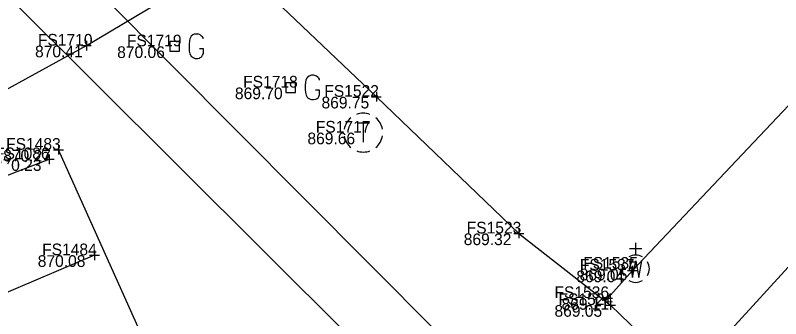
# Model space of a CAD drawing. Extents: x 1479420 to 1479833, y 379731 to 380103.
# Drawn here: x 1479593 to 1479671.7, y 379881 to 379912.2 of the extents above; entities that cross this region are included whole.
import ezdxf

# ---------------------------------------------------------------- set-up
doc = ezdxf.new("R2010")
doc.units = 0
for name, color, linetype in [('PM_X_Channelizing_Line', 7, 'Continuous'), ('PM_X_Crosswalk', 7, 'Continuous'), ('PM_X_Stop_Line', 7, 'Continuous'), ('PV_X_COP', 7, 'Continuous'), ('SV_X_Shot_Marker', 7, 'Continuous'), ('SV_X_Text_Elevation', 7, 'Continuous'), ('SV_X_Text_Name', 7, 'Continuous'), ('UT_X_Gas_Cells', 7, 'Continuous'), ('UT_X_Sanitary_Line', 7, 'Continuous'), ('UT_X_Telecom_Cells', 7, 'Continuous'), ('UT_X_Water', 7, 'Continuous'), ('UT_X_Water_Cells', 7, 'Continuous')]:
    doc.layers.add(name, color=color, linetype=linetype)

msp = doc.modelspace()

# ---------------------------------------------------------------- linework, layer by layer
at = {"layer": 'PM_X_Channelizing_Line'}
msp.add_line((1479601.101, 379887.483), (1479569.285, 379873.919), dxfattribs=at)
at = {"layer": 'PM_X_Crosswalk'}
for p, q in [((1479636.371, 379879.555), (1479574.01, 379942.241)), ((1479627.792, 379878.685), (1479575.124, 379931.128)), ((1479656.672, 379868.951), (1479694.216, 379910.084))]:
    msp.add_line(p, q, dxfattribs=at)
at = {"layer": 'PM_X_Stop_Line'}
msp.add_line((1479608.178, 379874.324), (1479597.401, 379898.33), dxfattribs=at)
at = {"layer": 'PV_X_COP'}
msp.add_lwpolyline([(1479441.789, 379822.02), (1479455.003, 379829.684), (1479469.105, 379838.412), (1479482.144, 379845.998), (1479493.535, 379852.152), (1479505.235, 379858.045), (1479517.8, 379863.732), (1479530.742, 379869.52), (1479544.647, 379875.382), (1479558.927, 379881.46), (1479574.038, 379887.901), (1479589.196, 379894.596), (1479596.439, 379897.36)], dxfattribs=at)
at = {"layer": 'SV_X_Shot_Marker'}
for p, q in [((1479600.276, 379909.545), (1479600.276, 379908.545)), ((1479599.776, 379909.045), (1479600.776, 379909.045)), ((1479600.276, 379909.045), (1479600.276, 379909.045)), ((1479630.106, 379904.283), (1479630.106, 379903.283)), ((1479629.606, 379903.783), (1479630.606, 379903.783)), ((1479630.106, 379903.783), (1479630.106, 379903.783)), ((1479596.901, 379898.33), (1479597.901, 379898.33)), ((1479597.401, 379898.83), (1479597.401, 379897.83)), ((1479597.401, 379898.33), (1479597.401, 379898.33)), ((1479596.439, 379897.86), (1479596.439, 379896.86)), ((1479595.939, 379897.36), (1479596.939, 379897.36)), ((1479596.439, 379897.36), (1479596.439, 379897.36)), ((1479644.269, 379889.722), (1479645.269, 379889.722)), ((1479644.769, 379890.222), (1479644.769, 379889.222)), ((1479644.769, 379889.722), (1479644.769, 379889.722)), ((1479600.601, 379887.483), (1479601.601, 379887.483)), ((1479601.101, 379887.983), (1479601.101, 379886.983)), ((1479601.101, 379887.483), (1479601.101, 379887.483)), ((1479655.953, 379885.901), (1479656.953, 379885.901)), ((1479656.453, 379886.401), (1479656.453, 379885.401)), ((1479656.453, 379885.901), (1479656.453, 379885.901)), ((1479653.917, 379883.575), (1479653.917, 379882.575)), ((1479653.417, 379883.075), (1479654.417, 379883.075)), ((1479653.917, 379883.075), (1479653.917, 379883.075)), ((1479654.209, 379882.856), (1479654.209, 379881.856)), ((1479653.709, 379882.356), (1479654.709, 379882.356)), ((1479654.209, 379882.356), (1479654.209, 379882.356))]:
    msp.add_line(p, q, dxfattribs=at)
at = {"layer": 'UT_X_Gas_Cells'}
for points in [[(1479612.305, 379909.737), (1479612.286, 379909.836), (1479612.227, 379909.934), (1479612.128, 379910.033), (1479611.991, 379910.151), (1479611.892, 379910.19), (1479611.813, 379910.21), (1479611.695, 379910.23), (1479611.459, 379910.23), (1479611.361, 379910.21), (1479611.301, 379910.19), (1479611.223, 379910.151), (1479611.065, 379910.033), (1479610.967, 379909.895), (1479610.908, 379909.737), (1479610.868, 379909.521), (1479610.829, 379909.206), (1479610.829, 379908.793), (1479610.849, 379908.458), (1479610.928, 379908.202), (1479611.046, 379907.966), (1479611.144, 379907.887), (1479611.262, 379907.808), (1479611.479, 379907.73), (1479611.695, 379907.73), (1479611.912, 379907.769), (1479611.991, 379907.808), (1479612.069, 379907.848), (1479612.148, 379907.926), (1479612.227, 379908.045), (1479612.305, 379908.222), (1479612.305, 379908.714), (1479611.892, 379908.714)], [(1479608.842, 379908.473), (1479609.842, 379908.473), (1479609.842, 379909.473), (1479608.842, 379909.473), (1479608.842, 379908.473)], [(1479624.263, 379905.497), (1479624.244, 379905.596), (1479624.185, 379905.694), (1479624.086, 379905.793), (1479623.949, 379905.911), (1479623.85, 379905.95), (1479623.771, 379905.97), (1479623.653, 379905.989), (1479623.417, 379905.989), (1479623.319, 379905.97), (1479623.259, 379905.95), (1479623.181, 379905.911), (1479623.023, 379905.793), (1479622.925, 379905.655), (1479622.866, 379905.497), (1479622.826, 379905.281), (1479622.787, 379904.966), (1479622.787, 379904.552), (1479622.807, 379904.218), (1479622.886, 379903.962), (1479623.004, 379903.726), (1479623.102, 379903.647), (1479623.22, 379903.568), (1479623.437, 379903.489), (1479623.653, 379903.489), (1479623.87, 379903.529), (1479623.949, 379903.568), (1479624.027, 379903.607), (1479624.106, 379903.686), (1479624.185, 379903.804), (1479624.263, 379903.982), (1479624.263, 379904.474), (1479623.85, 379904.474)], [(1479620.8, 379904.233), (1479621.8, 379904.233), (1479621.8, 379905.233), (1479620.8, 379905.233), (1479620.8, 379904.233)]]:
    msp.add_lwpolyline(points, dxfattribs=at)
at = {"layer": 'UT_X_Sanitary_Line'}
msp.add_lwpolyline([(1479514.622, 379866.87), (1479542.109, 379880.195), (1479565.169, 379891.725), (1479588.442, 379902.577), (1479600.276, 379909.045), (1479620.421, 379921.063), (1479621.963, 379921.485), (1479624.647, 379923.417), (1479645.234, 379932.512), (1479652.585, 379935.616), (1479664.157, 379939.675), (1479679.103, 379944.837), (1479710.112, 379956.448), (1479736.037, 379968.233), (1479798.147, 379991.168), (1479820.4, 379999.933), (1479823.042, 380000.22)], dxfattribs=at)
at = {"layer": 'UT_X_Telecom_Cells'}
for p, q in [((1479628.118, 379901.096), (1479629.418, 379901.096)), ((1479628.768, 379899.096), (1479628.768, 379901.096)), ((1479628.768, 379900.096), (1479628.768, 379900.096))]:
    msp.add_line(p, q, dxfattribs=at)
for start, end in [(130.0806, 170.07213), (70.05767, 110.10608), (10.01689, 50.03919), (190.01689, 230.03919), (310.01144, 350.02638), (250.05767, 290.04731)]:
    msp.add_arc((1479628.767, 379900.095), 2, start, end, dxfattribs=at)
at = {"layer": 'UT_X_Water'}
for points in [[(1479473.217, 380054.881), (1479498.741, 380029.974), (1479514.505, 380014.086), (1479533.448, 379996.735), (1479556.003, 379974.319), (1479574.861, 379956.271), (1479584.403, 379947.432), (1479599.597, 379932.819), (1479630.106, 379903.783), (1479644.769, 379889.722), (1479654.209, 379882.356), (1479664.266, 379872.629), (1479692.509, 379845.847), (1479712.672, 379826.686), (1479730.739, 379809.85), (1479753.15, 379788.309), (1479771.842, 379770.542), (1479781.678, 379761.101)], [(1479653.917, 379883.075), (1479656.453, 379885.901), (1479682.649, 379913.582), (1479686.182, 379917.14), (1479686.736, 379917.656), (1479692.788, 379923.268), (1479699.703, 379929.77), (1479707.876, 379935.91), (1479714.6, 379939.488), (1479720.618, 379942.792), (1479734.686, 379951.003), (1479759.021, 379964.62), (1479771.505, 379971.304), (1479799.27, 379984.838)]]:
    msp.add_lwpolyline(points, dxfattribs=at)
at = {"layer": 'UT_X_Water_Cells'}
for p, q in [((1479657.436, 379888.13), (1479656.164, 379888.13)), ((1479656.801, 379887.494), (1479656.801, 379888.765)), ((1479656.801, 379886.094), (1479656.801, 379886.094))]:
    msp.add_line(p, q, dxfattribs=at)
msp.add_lwpolyline([(1479656.164, 379886.914), (1479656.483, 379885.19), (1479656.801, 379886.914), (1479657.121, 379885.19), (1479657.438, 379886.914)], dxfattribs=at)
for start, end in [(60.01836, 120.01574), (150.01836, 209.98164), (330.01836, 29.98164), (239.98426, 299.98164)]:
    msp.add_arc((1479656.801, 379886.095), 1.4, start, end, dxfattribs=at)

# ---------------------------------------------------------------- texts
at = {"layer": 'SV_X_Text_Elevation'}
for s, p in [('870.41', (1479594.984, 379907.845)), ('870.06', (1479603.437, 379907.773)), ('869.70', (1479615.555, 379903.533)), ('869.75', (1479624.465, 379902.583)), ('869.66', (1479623.014, 379898.896)), ('870.27', (1479591.704, 379897.13)), ('870.23', (1479590.742, 379896.16)), ('869.32', (1479639.1, 379888.522)), ('870.08', (1479595.262, 379886.283)), ('869.04', (1479650.69, 379884.701)), ('869.05', (1479651.028, 379884.894)), ('869.11', (1479649.164, 379881.875)), ('869.05', (1479648.436, 379881.156))]:
    msp.add_text(s, height=1.2, dxfattribs=at).set_placement(p)
at = {"layer": 'SV_X_Text_Name'}
for s, p in [('FS1710', (1479595.279, 379909.045)), ('FS1719', (1479604.44, 379908.973)), ('FS1718', (1479616.398, 379904.733)), ('FS1522', (1479624.75, 379903.783)), ('FS1717', (1479623.875, 379900.096)), ('FS1483', (1479592.007, 379898.33)), ('FS1086', (1479590.865, 379897.36)), ('FS1523', (1479639.403, 379889.722)), ('FS1484', (1479595.716, 379887.483)), ('FS1535', (1479651.397, 379886.094)), ('FS1537', (1479651.049, 379885.901)), ('FS1536', (1479648.438, 379883.075)), ('FS1524', (1479648.853, 379882.356))]:
    msp.add_text(s, height=1.2, dxfattribs=at).set_placement(p)

doc.saveas('drawing.dxf')
